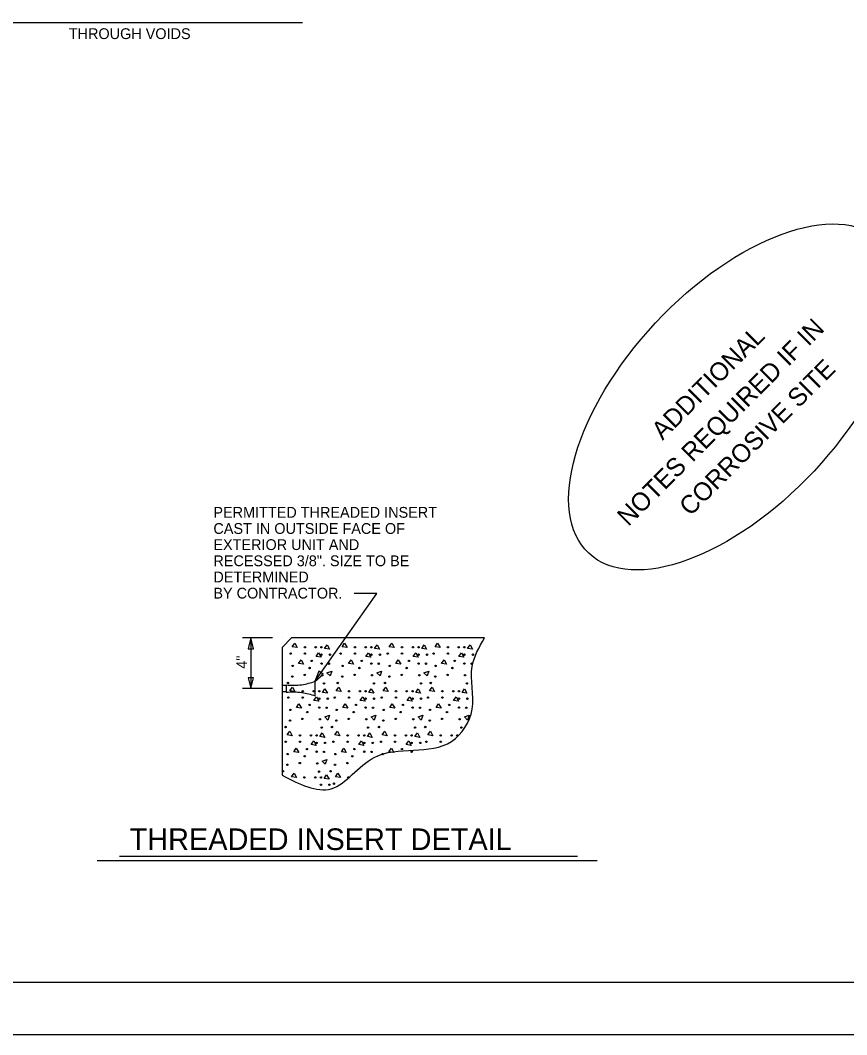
# Model space of a CAD drawing. Extents: x -38 to 94, y -165 to 80.
# Drawn here: x 29.11 to 54.62, y 16.93 to 48.24 of the extents above; entities that cross this region are included whole.
import ezdxf

# ---------------------------------------------------------------- set-up
doc = ezdxf.new("R2010")
doc.units = 0
for name, color, linetype in [('Arrowhead Terminators CELL', 7, 'Continuous'), ('Box Beam', 7, 'Continuous'), ('Dimension Lines', 7, 'Continuous'), ('Plan Sheet CELL', 7, 'Continuous'), ('Plot Shape CELL', 7, 'Continuous'), ('Rebar Lines', 7, 'Continuous'), ('Rebar Lines CELL', 7, 'Continuous'), ('Subtitle Text', 7, 'Continuous'), ('Sup Concrete Girder Lines', 7, 'Continuous'), ('Text', 7, 'Continuous'), ('Title Text', 7, 'Continuous'), ('User Information Notes', 7, 'Continuous')]:
    doc.layers.add(name, color=color, linetype=linetype)

msp = doc.modelspace()

# ---------------------------------------------------------------- linework, layer by layer
at = {"layer": 'Arrowhead Terminators CELL'}
for points in [[(36.226, 29.173), (36.142, 28.839), (36.309, 28.839)], [(36.226, 27.612), (36.309, 27.945), (36.142, 27.945)], [(38.199, 27.83), (38.46, 28.055), (38.324, 28.151)], [(38.199, 27.83), (38.46, 28.055), (38.324, 28.151)]]:
    msp.add_lwpolyline(points, close=True, dxfattribs=at)
at = {"layer": 'Box Beam'}
for points in [[(37.504, 28.902), (37.584, 29.016), (37.658, 28.88), (37.504, 28.902)], [(38.506, 28.849), (38.586, 28.963), (38.66, 28.827), (38.506, 28.849)], [(39.044, 28.902), (39.124, 29.016), (39.197, 28.88), (39.044, 28.902)], [(40.046, 28.849), (40.126, 28.963), (40.2, 28.827), (40.046, 28.849)], [(40.5, 28.902), (40.579, 29.016), (40.653, 28.88), (40.5, 28.902)], [(41.502, 28.849), (41.582, 28.963), (41.655, 28.827), (41.502, 28.849)], [(41.914, 28.902), (41.993, 29.016), (42.067, 28.88), (41.914, 28.902)], [(42.916, 28.849), (42.995, 28.963), (43.069, 28.827), (42.916, 28.849)], [(37.705, 28.384), (37.784, 28.498), (37.858, 28.362), (37.705, 28.384)], [(38.243, 28.603), (38.322, 28.717), (38.396, 28.581), (38.243, 28.603)], [(39.245, 28.384), (39.324, 28.498), (39.398, 28.362), (39.245, 28.384)], [(39.783, 28.603), (39.862, 28.717), (39.936, 28.581), (39.783, 28.603)], [(40.7, 28.384), (40.78, 28.498), (40.854, 28.362), (40.7, 28.384)], [(41.238, 28.603), (41.318, 28.717), (41.392, 28.581), (41.238, 28.603)], [(42.114, 28.384), (42.194, 28.498), (42.267, 28.362), (42.114, 28.384)], [(42.652, 28.603), (42.732, 28.717), (42.806, 28.581), (42.652, 28.603)], [(38.676, 27.999), (38.578, 28.098), (38.725, 28.146), (38.676, 27.999)], [(40.216, 27.999), (40.118, 28.098), (40.265, 28.146), (40.216, 27.999)], [(41.672, 27.999), (41.573, 28.098), (41.72, 28.146), (41.672, 27.999)], [(37.435, 27.543), (37.514, 27.657), (37.588, 27.521), (37.435, 27.543)], [(38.437, 27.49), (38.516, 27.604), (38.59, 27.468), (38.437, 27.49)], [(38.865, 27.543), (38.945, 27.657), (39.019, 27.521), (38.865, 27.543)], [(39.867, 27.49), (39.947, 27.604), (40.021, 27.468), (39.867, 27.49)], [(40.314, 27.543), (40.394, 27.657), (40.467, 27.521), (40.314, 27.543)], [(41.316, 27.49), (41.396, 27.604), (41.47, 27.468), (41.316, 27.49)], [(41.745, 27.543), (41.824, 27.657), (41.898, 27.521), (41.745, 27.543)], [(42.747, 27.49), (42.827, 27.604), (42.9, 27.468), (42.747, 27.49)], [(38.173, 27.244), (38.253, 27.358), (38.326, 27.222), (38.173, 27.244)], [(39.604, 27.244), (39.683, 27.358), (39.757, 27.222), (39.604, 27.244)], [(41.053, 27.244), (41.132, 27.358), (41.206, 27.222), (41.053, 27.244)], [(42.483, 27.244), (42.563, 27.358), (42.637, 27.222), (42.483, 27.244)], [(37.635, 27.025), (37.715, 27.139), (37.788, 27.003), (37.635, 27.025)], [(39.066, 27.025), (39.145, 27.139), (39.219, 27.003), (39.066, 27.025)], [(40.515, 27.025), (40.594, 27.139), (40.668, 27.003), (40.515, 27.025)], [(41.945, 27.025), (42.025, 27.139), (42.099, 27.003), (41.945, 27.025)], [(38.606, 26.64), (38.508, 26.739), (38.655, 26.787), (38.606, 26.64)], [(40.037, 26.64), (39.939, 26.739), (40.086, 26.787), (40.037, 26.64)], [(41.486, 26.64), (41.388, 26.739), (41.535, 26.787), (41.486, 26.64)], [(42.916, 26.64), (42.818, 26.739), (42.965, 26.787), (42.916, 26.64)], [(37.353, 26.18), (37.432, 26.293), (37.506, 26.157), (37.353, 26.18)], [(38.091, 25.881), (38.171, 25.994), (38.244, 25.858), (38.091, 25.881)], [(38.355, 26.127), (38.434, 26.241), (38.508, 26.104), (38.355, 26.127)], [(38.822, 26.18), (38.902, 26.293), (38.976, 26.157), (38.822, 26.18)], [(39.561, 25.881), (39.641, 25.994), (39.714, 25.858), (39.561, 25.881)], [(39.825, 26.127), (39.904, 26.241), (39.978, 26.104), (39.825, 26.127)], [(40.286, 26.18), (40.366, 26.293), (40.439, 26.157), (40.286, 26.18)], [(41.025, 25.881), (41.104, 25.994), (41.178, 25.858), (41.025, 25.881)], [(41.288, 26.127), (41.368, 26.241), (41.442, 26.104), (41.288, 26.127)], [(41.694, 26.18), (41.774, 26.293), (41.847, 26.157), (41.694, 26.18)], [(37.553, 25.662), (37.633, 25.775), (37.706, 25.639), (37.553, 25.662)], [(39.023, 25.662), (39.103, 25.775), (39.176, 25.639), (39.023, 25.662)], [(40.487, 25.662), (40.566, 25.775), (40.64, 25.639), (40.487, 25.662)], [(38.524, 25.277), (38.426, 25.375), (38.573, 25.424), (38.524, 25.277)], [(37.487, 24.885), (37.566, 24.999), (37.64, 24.863), (37.487, 24.885)], [(38.489, 24.832), (38.568, 24.946), (38.642, 24.81), (38.489, 24.832)], [(38.838, 24.885), (38.918, 24.999), (38.992, 24.863), (38.838, 24.885)]]:
    msp.add_lwpolyline(points, dxfattribs=at)
for centre in [(37.899, 28.886), (38.233, 28.886), (38.409, 28.886), (39.439, 28.886), (39.773, 28.886), (39.949, 28.886), (40.895, 28.886), (41.229, 28.886), (41.405, 28.886), (42.309, 28.886), (42.643, 28.886), (42.819, 28.886), (37.46, 28.693), (37.899, 28.693), (38.409, 28.657), (38.673, 28.657), (38.999, 28.693), (39.439, 28.693), (39.949, 28.657), (40.213, 28.657), (40.455, 28.693), (40.895, 28.693), (41.405, 28.657), (41.669, 28.657), (41.869, 28.693), (42.309, 28.693), (42.819, 28.657), (43.082, 28.657), (37.52, 28.312), (38.041, 28.245), (38.11, 28.464), (38.41, 28.384), (38.637, 28.379), (39.06, 28.312), (39.581, 28.245), (39.65, 28.464), (39.95, 28.384), (40.177, 28.379), (40.515, 28.312), (41.037, 28.245), (41.106, 28.464), (41.405, 28.384), (41.632, 28.379), (41.929, 28.312), (42.45, 28.245), (42.52, 28.464), (42.819, 28.384), (43.046, 28.379), (37.509, 27.981), (37.892, 28.032), (38.431, 28.022), (39.049, 27.981), (39.432, 28.032), (39.97, 28.022), (40.505, 27.981), (40.888, 28.032), (41.426, 28.022), (41.919, 27.981), (42.302, 28.032), (42.84, 28.022), (37.371, 27.783), (38.488, 27.768), (38.911, 27.783), (40.028, 27.768), (40.367, 27.783), (41.483, 27.768), (41.781, 27.783), (42.897, 27.768), (37.39, 27.334), (37.83, 27.527), (37.83, 27.334), (38.164, 27.527), (38.34, 27.527), (38.34, 27.298), (38.603, 27.298), (38.821, 27.334), (39.26, 27.527), (39.26, 27.334), (39.594, 27.527), (39.77, 27.527), (39.77, 27.298), (40.034, 27.298), (40.27, 27.334), (40.709, 27.527), (40.709, 27.334), (41.043, 27.527), (41.219, 27.527), (41.219, 27.298), (41.483, 27.298), (41.7, 27.334), (42.14, 27.527), (42.14, 27.334), (42.474, 27.527), (42.65, 27.527), (42.65, 27.298), (42.914, 27.298), (37.45, 26.953), (38.041, 27.105), (38.34, 27.025), (38.567, 27.02), (38.881, 26.953), (39.471, 27.105), (39.771, 27.025), (39.998, 27.02), (40.33, 26.953), (40.92, 27.105), (41.22, 27.025), (41.447, 27.02), (41.76, 26.953), (42.351, 27.105), (42.65, 27.025), (42.877, 27.02), (37.44, 26.622), (37.823, 26.674), (37.971, 26.886), (38.361, 26.663), (38.87, 26.622), (39.253, 26.674), (39.402, 26.886), (39.791, 26.663), (40.319, 26.622), (40.702, 26.674), (40.851, 26.886), (41.24, 26.663), (41.75, 26.622), (42.133, 26.674), (42.282, 26.886), (42.671, 26.663), (37.302, 26.424), (38.418, 26.409), (38.732, 26.424), (39.849, 26.409), (40.181, 26.424), (41.298, 26.409), (41.612, 26.424), (42.728, 26.409), (37.308, 25.97), (37.748, 26.164), (37.748, 25.97), (38.082, 26.164), (38.258, 26.164), (38.778, 25.97), (39.217, 26.164), (39.217, 25.97), (39.552, 26.164), (39.727, 26.164), (40.242, 25.97), (40.681, 26.164), (40.681, 25.97), (41.015, 26.164), (41.191, 26.164), (41.649, 25.97), (42.089, 26.164), (42.089, 25.97), (42.423, 26.164), (42.599, 26.164), (37.959, 25.741), (38.258, 25.935), (38.258, 25.662), (38.485, 25.657), (38.521, 25.935), (39.428, 25.741), (39.727, 25.935), (39.728, 25.662), (39.955, 25.657), (39.991, 25.935), (40.892, 25.741), (41.191, 25.935), (41.192, 25.662), (41.455, 25.935), (37.368, 25.589), (37.889, 25.522), (38.838, 25.589), (39.359, 25.522), (40.302, 25.589), (37.219, 25.061), (37.358, 25.258), (37.741, 25.31), (38.279, 25.3), (38.336, 25.046), (38.689, 25.061), (38.827, 25.258), (39.21, 25.31), (37.882, 24.869), (38.216, 24.869), (38.392, 24.869), (39.233, 24.869), (38.392, 24.64), (38.655, 24.64), (38.794, 24.675)]:
    msp.add_circle(centre, 0.0219, dxfattribs=at)
at = {"layer": 'Dimension Lines'}
for p, q in [((36.898, 29.173), (35.974, 29.173)), ((36.226, 29.173), (36.226, 27.612)), ((36.898, 27.612), (35.974, 27.612))]:
    msp.add_line(p, q, dxfattribs=at)
msp.add_lwpolyline([(38.199, 27.83), (40.119, 30.542), (39.417, 30.542)], dxfattribs=at)
at = {"layer": 'Plan Sheet CELL'}
msp.add_line((-9.472, 18.545), (75.969, 18.545), dxfattribs=at)
at = {"layer": 'Plot Shape CELL'}
msp.add_lwpolyline([(-12.286, 75.667), (75.992, 75.667), (75.992, 16.927), (-12.286, 16.927)], close=True, dxfattribs=at)
at = {"layer": 'Rebar Lines'}
for p, q in [((37.323, 27.709), (37.193, 27.709)), ((37.323, 27.514), (37.193, 27.514))]:
    msp.add_line(p, q, dxfattribs=at)
at = {"layer": 'Rebar Lines CELL'}
for p, q in [((38.212, 27.612), (38.212, 27.834)), ((38.212, 27.39), (38.212, 27.612))]:
    msp.add_line(p, q, dxfattribs=at)
for points in [[(37.323, 27.722), (37.803, 27.731), (38.212, 27.834)], [(37.323, 27.501), (37.803, 27.492), (38.212, 27.39)]]:
    msp.add_spline(points, degree=3, dxfattribs=at)
at = {"layer": 'Subtitle Text'}
msp.add_line((37.819, 48.159), (27.412, 48.159), dxfattribs=at)
at = {"layer": 'Sup Concrete Girder Lines'}
msp.add_lwpolyline([(43.444, 29.173), (37.486, 29.173), (37.193, 28.88), (37.193, 24.933)], dxfattribs=at)
msp.add_spline([(37.193, 24.933), (38.709, 24.52), (40.031, 25.484), (42.426, 25.98), (43.059, 26.972), (43.059, 28.294), (43.444, 29.173)], degree=3, dxfattribs=at)
at = {"layer": 'Text'}
msp.add_line((37.323, 27.722), (37.323, 27.501), dxfattribs=at)
at = {"layer": 'Title Text'}
for p, q in [((31.482, 22.304), (46.922, 22.304)), ((32.173, 22.438), (46.315, 22.438))]:
    msp.add_line(p, q, dxfattribs=at)
at = {"layer": 'User Information Notes'}
msp.add_line((37.193, 29.173), (37.193, 29.173), dxfattribs=at)
msp.add_ellipse((51.167, 36.612), major_axis=(4.509, 4.826), ratio=0.506929, dxfattribs=at)

# ---------------------------------------------------------------- texts
at = {"layer": 'Text'}
for s, p in [('THROUGH VOIDS', (30.61, 47.659)), ('PERMITTED THREADED INSERT', (35.073, 32.884)), ('CAST IN OUTSIDE FACE OF ', (35.073, 32.385)), ('EXTERIOR UNIT AND', (35.073, 31.887)), ('RECESSED 3/8". SIZE TO BE ', (35.073, 31.388)), ('DETERMINED', (35.073, 30.889)), ('BY CONTRACTOR.', (35.073, 30.39))]:
    msp.add_text(s, height=0.333, dxfattribs=at).set_placement(p)
msp.add_text('4"', height=0.333, rotation=90, dxfattribs=at).set_placement((36.113, 28.223))
at = {"layer": 'Title Text'}
msp.add_text('THREADED INSERT DETAIL', height=0.667, dxfattribs=at).set_placement((32.487, 22.627))
at = {"layer": 'User Information Notes'}
for s, p in [('NOTES REQUIRED IF IN', (47.879, 32.596)), ('ADDITIONAL', (48.937, 35.255)), ('CORROSIVE SITE', (49.792, 32.91))]:
    msp.add_text(s, height=0.5625, rotation=45, dxfattribs=at).set_placement(p)

doc.saveas('drawing.dxf')
